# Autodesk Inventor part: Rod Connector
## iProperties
Shininess: 64.0
Length Units: 11272
Angle Units: 11279
Time Units: 11290
Mass Units: 11286
Length Display Precision: 3
Angle Display Precision: 2
Compacted: True
Part Number: Rod Connector
Document SubType Name: Modeling
Created: 2003-08
Designer: jpittman
Manufacturer: Standard
Standards Organization: Custom
Density: 0.0
Volumn: 0.0
Area: 0.0
PropertySet Name: Model Information
Control State: 0
Master: False
Checked Out: False
Author: jpittman
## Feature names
1. Extrusion1
2. Hole2
